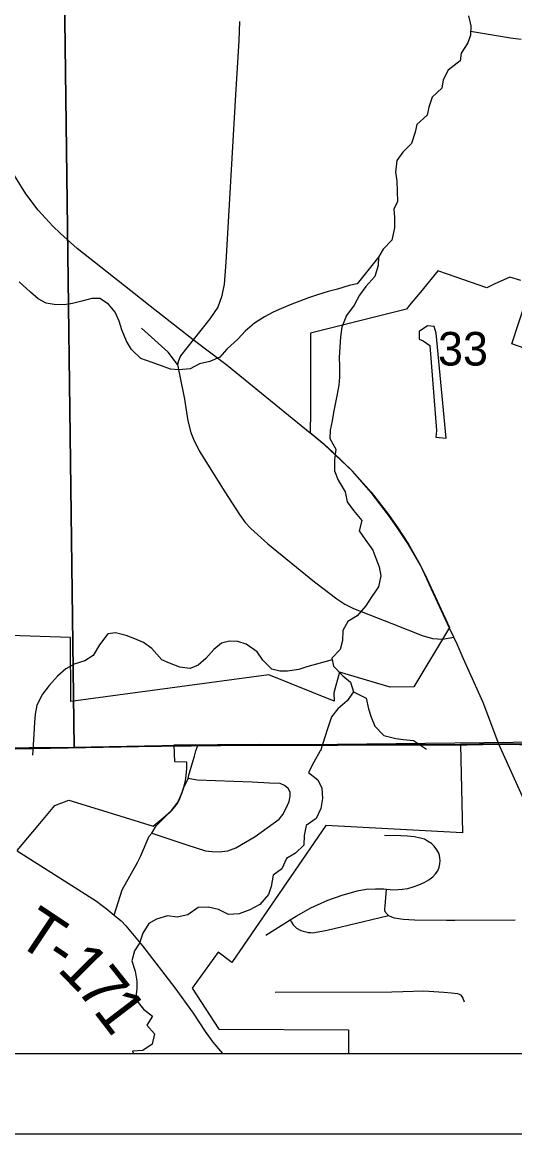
# Model space of a CAD drawing. Extents: x 0 to 36.9, y 0 to 22.
# Drawn here: x 6.188 to 6.801, y 14 to 15.386 of the extents above; entities that cross this region are included whole.
import ezdxf

# ---------------------------------------------------------------- set-up
doc = ezdxf.new("R2010")
doc.units = 0
for name, color, linetype in [('Default', 7, 'Continuous'), ('GM_X_City_Street', 7, 'Continuous'), ('GM_X_County_Road', 7, 'Continuous'), ('GM_X_Major_River', 7, 'Continuous'), ('GM_X_Minor_Lake', 7, 'Continuous'), ('GM_X_Minor_River', 7, 'Continuous'), ('GM_X_Rail_Line', 7, 'Continuous'), ('GM_X_Section', 7, 'Continuous'), ('GM_X_Section_Text', 7, 'Continuous'), ('GM_X_State_Route', 7, 'Continuous'), ('GM_X_Township_Road', 7, 'Continuous'), ('GM_X_Township_Road_Text', 7, 'Continuous'), ('SH_Cut_Line', 7, 'Continuous'), ('SH_Data', 7, 'Continuous')]:
    doc.layers.add(name, color=color, linetype=linetype)

msp = doc.modelspace()

# ---------------------------------------------------------------- linework, layer by layer
at = {"layer": 'Default'}
for points in [[(6.8088, 15.0639), (6.7952, 15.0679), (6.7758, 15.0591), (6.7664, 15.0548), (6.7177, 15.0717), (6.7056, 15.0759), (6.6858, 15.0518), (6.6704, 15.0331), (6.6663, 15.0282), (6.5467, 14.9982), (6.5468, 14.8917), (6.5466, 14.8829), (6.5463, 14.8742), (6.5641, 14.8596), (6.5751, 14.8492), (6.5989, 14.8266), (6.6223, 14.8), (6.644, 14.772), (6.6557, 14.7553), (6.6688, 14.7351), (6.6837, 14.7095), (6.6917, 14.6923), (6.72, 14.631), (6.6757, 14.5571), (6.646, 14.5566), (6.583, 14.5755), (6.576, 14.5497), (6.5762, 14.5395), (6.4949, 14.5722), (6.2485, 14.5389), (6.2478, 14.6189), (6.1594, 14.6218)], [(6.8534, 14.9652), (6.7979, 14.9848), (6.8153, 15.0379)], [(6.1813, 14.3532), (6.2097, 14.3868), (6.2286, 14.4091), (6.2459, 14.416), (6.2984, 14.3998), (6.3509, 14.3835), (6.3659, 14.3958), (6.3736, 14.4031), (6.381, 14.4123), (6.384, 14.4188), (6.3869, 14.426), (6.389, 14.4321), (6.3912, 14.4405), (6.3919, 14.4464), (6.3925, 14.4517), (6.3927, 14.4546), (6.393, 14.4631), (6.3779, 14.4636), (6.377, 14.4847), (6.485, 14.4856), (6.5771, 14.4855), (6.7336, 14.4854), (6.7364, 14.3753), (6.5661, 14.3843), (6.4487, 14.2137), (6.432, 14.2263), (6.3995, 14.1816), (6.4327, 14.1303), (6.5942, 14.1297), (6.5942, 14.1), (7.9756, 14.1)]]:
    msp.add_lwpolyline(points, dxfattribs=at)
at = {"layer": 'GM_X_City_Street'}
msp.add_line((6.844, 14.3471), (6.7814, 14.4858), dxfattribs=at)
for points in [[(6.4911, 14.2476), (6.5216, 14.2667), (6.529, 14.2714), (6.5472, 14.2815), (6.5685, 14.2911), (6.5863, 14.2974), (6.6051, 14.3027), (6.6164, 14.3048), (6.6278, 14.3054), (6.6384, 14.3052), (6.6415, 14.3049), (6.6506, 14.3043), (6.6612, 14.3048), (6.6682, 14.3059), (6.675, 14.3077), (6.6817, 14.3102), (6.6886, 14.3134), (6.6944, 14.3167), (6.6992, 14.3203), (6.7027, 14.3242), (6.7055, 14.328), (6.7073, 14.3323), (6.7081, 14.3364), (6.7083, 14.3405), (6.7082, 14.344), (6.7077, 14.3471), (6.7067, 14.3497), (6.7044, 14.3541), (6.7008, 14.3587), (6.6975, 14.3618), (6.6928, 14.365), (6.6888, 14.3671), (6.684, 14.3686), (6.676, 14.3701), (6.6677, 14.3711), (6.6593, 14.3716), (6.6391, 14.3717)], [(6.6439, 14.2722), (6.6422, 14.2738), (6.6409, 14.2753), (6.6402, 14.2765), (6.6397, 14.2776), (6.6395, 14.2793), (6.6396, 14.2805), (6.6399, 14.2839), (6.6415, 14.3049)], [(6.5216, 14.2667), (6.5232, 14.2637), (6.5252, 14.2606), (6.5272, 14.2583), (6.5296, 14.2562), (6.5349, 14.2536), (6.5379, 14.2525), (6.5412, 14.2516), (6.5442, 14.2511), (6.5472, 14.2508), (6.5497, 14.2507), (6.5517, 14.2509), (6.5676, 14.2538), (6.6129, 14.2645), (6.6439, 14.2722), (6.6477, 14.2704), (6.651, 14.2694), (6.6541, 14.2687), (6.6622, 14.2676), (6.6766, 14.2667), (6.7165, 14.2662), (6.7267, 14.2661), (6.8019, 14.2666)], [(6.5029, 14.1767), (6.6482, 14.177), (6.6619, 14.1774), (6.6881, 14.1781), (6.7128, 14.1766), (6.7227, 14.1759), (6.7263, 14.1755), (6.7299, 14.175), (6.7321, 14.1742), (6.7337, 14.1731), (6.7355, 14.1713), (6.7368, 14.169), (6.7384, 14.1645)]]:
    msp.add_lwpolyline(points, dxfattribs=at)
at = {"layer": 'GM_X_County_Road'}
for points in [[(6.4585, 15.3868), (6.4576, 15.363), (6.4533, 15.2954), (6.4415, 15.0867), (6.4393, 15.0589), (6.436, 15.0433), (6.4313, 15.0306), (6.4216, 15.0161), (6.4006, 14.9897)], [(6.3813, 14.959), (6.3694, 14.9743), (6.3365, 15.0042)], [(6.4006, 14.9897), (6.3851, 14.9697), (6.3823, 14.9637), (6.3813, 14.959), (6.3843, 14.9447), (6.3899, 14.9159), (6.3942, 14.8889), (6.3978, 14.8745), (6.401, 14.8659), (6.4084, 14.8514), (6.4401, 14.8005), (6.4583, 14.7719), (6.4656, 14.762), (6.4724, 14.7547), (6.4937, 14.7356), (6.5519, 14.688), (6.5798, 14.6668), (6.5896, 14.6604), (6.6005, 14.6547), (6.6481, 14.6362), (6.6859, 14.6214), (6.6987, 14.6173), (6.7112, 14.6167), (6.7254, 14.6192)]]:
    msp.add_lwpolyline(points, dxfattribs=at)
at = {"layer": 'GM_X_Major_River'}
for points in [[(6.7438, 15.3937), (6.7467, 15.3812), (6.7461, 15.3698), (6.7429, 15.3603), (6.7347, 15.3472), (6.7334, 15.3377), (6.7184, 15.326), (6.7122, 15.3138), (6.7105, 15.3035), (6.6985, 15.2923), (6.6942, 15.28), (6.6921, 15.2701), (6.6794, 15.2585), (6.6773, 15.2486), (6.6726, 15.2345), (6.6621, 15.2237), (6.6543, 15.2136), (6.6527, 15.1988), (6.6544, 15.1882), (6.6547, 15.1749), (6.6553, 15.1624), (6.6509, 15.1529), (6.6514, 15.1422), (6.6517, 15.1293), (6.6482, 15.1141), (6.6373, 15.1029), (6.6318, 15.0929)], [(6.6318, 15.0929), (6.6312, 15.0827), (6.6269, 15.0689), (6.6158, 15.0562), (6.608, 15.0454), (6.6014, 15.0331), (6.5917, 15.0201), (6.5859, 15.0055), (6.5842, 14.9937), (6.5833, 14.9808), (6.5828, 14.9679), (6.583, 14.9569), (6.5829, 14.9432), (6.5823, 14.9334), (6.5795, 14.92), (6.5778, 14.9097), (6.5757, 14.8991), (6.574, 14.8888), (6.5715, 14.8774), (6.5709, 14.8667), (6.5784, 14.8536), (6.5767, 14.8403), (6.5766, 14.8266), (6.5814, 14.8149), (6.59, 14.8003), (6.5925, 14.7878), (6.6003, 14.7769), (6.6107, 14.7646), (6.6075, 14.7516), (6.6149, 14.7411), (6.6247, 14.7276), (6.6283, 14.7178), (6.6323, 14.7069), (6.6344, 14.6955), (6.6316, 14.6818), (6.6231, 14.6699), (6.6157, 14.658), (6.6049, 14.6457), (6.5936, 14.6386), (6.587, 14.6275), (6.5868, 14.615), (6.584, 14.6039), (6.5735, 14.5931), (6.5756, 14.5829), (6.5872, 14.5709), (6.5969, 14.5631), (6.6005, 14.5511), (6.5927, 14.5399), (6.5811, 14.5298), (6.5729, 14.5198), (6.5675, 14.5038), (6.5592, 14.4774)]]:
    msp.add_lwpolyline(points, dxfattribs=at)
at = {"layer": 'GM_X_Minor_Lake'}
for points in [[(6.7036, 14.9983), (6.7008, 15.0066), (6.6928, 15.0072), (6.6823, 15.0002), (6.6821, 14.9907), (6.6874, 14.9885), (6.6955, 14.9826), (6.7037, 14.8768), (6.7031, 14.8684), (6.716, 14.8671)], [(6.716, 14.8671), (6.7036, 14.9983)]]:
    msp.add_lwpolyline(points, dxfattribs=at)
at = {"layer": 'GM_X_Minor_River'}
for points in [[(6.7463, 15.3745), (6.7959, 15.3665), (6.8092, 15.3645)], [(6.6318, 15.0929), (6.6049, 15.0597), (6.5951, 15.0576), (6.5807, 15.0532), (6.5689, 15.05), (6.5557, 15.0459), (6.5444, 15.042), (6.5338, 15.038), (6.5236, 15.0344), (6.5107, 15.0289), (6.5002, 15.0245), (6.4896, 15.0186), (6.4772, 15.0108), (6.4656, 15.0008), (6.457, 14.9911), (6.4427, 14.9784), (6.4338, 14.9684), (6.4213, 14.9628), (6.4088, 14.96), (6.3971, 14.9537), (6.3827, 14.9523), (6.3724, 14.9533), (6.3613, 14.9573), (6.3495, 14.9616), (6.3357, 14.9667), (6.3241, 14.9776), (6.3175, 14.9881), (6.3119, 15.0024), (6.3087, 15.013), (6.3036, 15.0243), (6.2954, 15.0344), (6.2843, 15.0414), (6.2744, 15.0413), (6.2619, 15.038), (6.2506, 15.0352), (6.24, 15.0335), (6.2274, 15.0337), (6.2175, 15.0354), (6.2075, 15.0409), (6.1979, 15.0491), (6.184, 15.0622)], [(6.574, 14.5909), (6.5422, 14.5823), (6.5324, 14.5787), (6.5184, 14.5769), (6.5089, 14.5767), (6.4986, 14.5792), (6.4874, 14.5904), (6.4804, 14.6009), (6.4669, 14.6105), (6.4562, 14.6138), (6.446, 14.6143), (6.4361, 14.6115), (6.4264, 14.6037), (6.4167, 14.5926), (6.407, 14.5844), (6.3968, 14.5801), (6.3843, 14.5817), (6.3713, 14.5868), (6.3617, 14.5908), (6.3493, 14.605), (6.3389, 14.6124), (6.3282, 14.6172), (6.3171, 14.6211), (6.3041, 14.6247), (6.2943, 14.6234), (6.2839, 14.6095), (6.2762, 14.5961), (6.2657, 14.5898), (6.2524, 14.5854), (6.2423, 14.5796), (6.2318, 14.5706), (6.2214, 14.5587), (6.2129, 14.5479), (6.2059, 14.5345), (6.2038, 14.5231), (6.2032, 14.5128), (6.2024, 14.4984), (6.2008, 14.4721)], [(6.6005, 14.5511), (6.6162, 14.543), (6.6191, 14.5298), (6.6223, 14.5192), (6.6271, 14.5083), (6.6383, 14.4967), (6.6532, 14.4928), (6.6627, 14.4915), (6.6752, 14.4905), (6.6913, 14.4793)], [(6.5591, 14.4775), (6.5512, 14.4633), (6.5443, 14.4506), (6.5562, 14.4413), (6.5609, 14.4308), (6.5619, 14.4179), (6.5598, 14.4057), (6.5539, 14.3931), (6.5416, 14.3842), (6.5391, 14.372), (6.5386, 14.3598), (6.5281, 14.3498), (6.5169, 14.3432), (6.5114, 14.3305), (6.5002, 14.3224), (6.4977, 14.3083), (6.4945, 14.2984), (6.4837, 14.2857), (6.4713, 14.279), (6.4581, 14.2742), (6.4449, 14.2732), (6.4323, 14.2795), (6.4197, 14.2827), (6.4068, 14.2821), (6.3941, 14.2731), (6.3809, 14.2699), (6.3687, 14.2719), (6.3551, 14.2675), (6.3454, 14.262), (6.338, 14.2501), (6.3337, 14.2376), (6.3277, 14.228), (6.3242, 14.2154), (6.3285, 14.2029), (6.3307, 14.1901), (6.3304, 14.1806), (6.3291, 14.1677), (6.3388, 14.1553), (6.35, 14.1468), (6.343, 14.1353), (6.3526, 14.1248), (6.3498, 14.1119), (6.3382, 14.1037), (6.3253, 14.1031), (6.3265, 14.1)]]:
    msp.add_lwpolyline(points, dxfattribs=at)
at = {"layer": 'GM_X_Rail_Line'}
msp.add_lwpolyline([(5.2462, 14.4712), (5.4467, 14.4748), (5.4581, 14.475), (5.4676, 14.4751), (5.9207, 14.4754), (6.4063, 14.4846), (6.5807, 14.485), (6.7336, 14.4854), (6.7812, 14.4863), (6.8569, 14.4852), (7.1313, 14.488), (7.4027, 14.4935), (7.7356, 14.4946), (7.9858, 14.497), (8.6137, 14.5116), (8.9, 14.5158), (8.9, 20.5927)], dxfattribs=at)
msp.add_lwpolyline([(4.2643, 14.1), (8.9, 14.1), (8.9, 14.5158), (8.6137, 14.5116), (7.9858, 14.497), (7.7356, 14.4946), (7.4027, 14.4935), (7.1313, 14.488), (6.8569, 14.4852), (6.7812, 14.4863), (6.7336, 14.4854), (6.5807, 14.485), (6.4063, 14.4846), (5.9207, 14.4754), (5.4676, 14.4751), (5.4581, 14.475), (5.4467, 14.4748), (5.2462, 14.4712), (5.1185, 14.4712), (4.6008, 14.4672), (4.262, 14.4619)], close=True, dxfattribs=at)
at = {"layer": 'GM_X_Section'}
for points in [[(6.2395, 15.4861), (7.2257, 15.5025), (7.2369, 14.4927), (6.2525, 14.4815)], [(5.2381, 15.4765), (6.2395, 15.4861), (6.2525, 14.4815), (5.2461, 14.474)]]:
    msp.add_lwpolyline(points, close=True, dxfattribs=at)
at = {"layer": 'GM_X_State_Route'}
for p, q in [((6.7372, 14.5928), (6.7294, 14.6104)), ((6.0398, 14.4771), (6.3767, 14.4835)), ((6.7417, 14.485), (6.7814, 14.4858)), ((6.7814, 14.4858), (6.8571, 14.4846))]:
    msp.add_line(p, q, dxfattribs=at)
for points in [[(6.3231, 15.051), (6.2562, 15.1039), (6.2353, 15.1223), (6.2258, 15.1314), (6.2075, 15.1513), (6.1924, 15.1718), (6.1795, 15.1927), (6.1563, 15.2327), (6.0155, 15.4812), (5.8461, 15.7824), (5.7784, 15.9063), (5.7307, 15.9951), (5.6955, 16.0767), (5.6648, 16.1701), (5.6378, 16.2518), (5.6249, 16.2792), (5.5961, 16.329), (5.5806, 16.3575), (5.5514, 16.4121), (5.5432, 16.4273), (5.5369, 16.4383), (5.504, 16.4959), (5.45, 16.5871)], [(6.5527, 14.8686), (6.5465, 14.8736), (6.4432, 14.9579), (6.4006, 14.9897), (6.3472, 15.0319), (6.3231, 15.051)], [(6.6953, 14.6843), (6.6919, 14.6917), (6.6839, 14.709), (6.669, 14.7345), (6.6559, 14.7547), (6.6442, 14.7714), (6.6225, 14.7995), (6.5991, 14.8261), (6.5643, 14.8591), (6.5527, 14.8686)], [(6.7294, 14.6104), (6.7254, 14.6192), (6.7202, 14.6305), (6.6953, 14.6843)], [(6.7814, 14.4858), (6.762, 14.5375), (6.7372, 14.5928)], [(6.3767, 14.4835), (6.4065, 14.4841), (6.574, 14.4845)], [(6.574, 14.4845), (6.5809, 14.4845), (6.6825, 14.4847)], [(6.6825, 14.4847), (6.7337, 14.4848), (6.7417, 14.485)]]:
    msp.add_lwpolyline(points, dxfattribs=at)
at = {"layer": 'GM_X_Township_Road'}
for points in [[(6.4022, 14.4706), (6.4042, 14.4775), (6.4065, 14.4841)], [(6.3548, 14.3839), (6.3656, 14.3948), (6.3742, 14.4029), (6.3812, 14.4117), (6.3842, 14.4182), (6.3871, 14.4255), (6.3892, 14.4316), (6.3946, 14.4428), (6.3958, 14.4487), (6.4022, 14.4706)], [(6.3493, 14.3747), (6.3927, 14.3602), (6.4163, 14.3529), (6.4246, 14.3518), (6.4331, 14.3516), (6.4438, 14.3529), (6.4539, 14.3566), (6.4779, 14.3706), (6.5006, 14.3869), (6.508, 14.3923), (6.5126, 14.398), (6.5166, 14.4061), (6.5203, 14.4141), (6.5214, 14.4211), (6.5214, 14.4259), (6.5189, 14.4304), (6.5144, 14.4344), (6.5093, 14.4368), (6.4957, 14.437), (6.4741, 14.4382), (6.4057, 14.4409), (6.3946, 14.4428)], [(6.3312, 14.3384), (6.3352, 14.3456), (6.346, 14.3709), (6.3493, 14.3747), (6.3548, 14.3839)], [(6.1814, 14.3527), (6.2576, 14.3047), (6.2802, 14.2898), (6.2859, 14.2858), (6.2925, 14.2808), (6.3024, 14.2727), (6.3109, 14.2653), (6.3169, 14.2592), (6.3377, 14.2343), (6.3777, 14.1821), (6.4006, 14.1502), (6.4157, 14.1273), (6.4254, 14.1142), (6.4347, 14.103), (6.4372, 14.1)], [(6.3024, 14.2727), (6.3121, 14.304), (6.3312, 14.3384)]]:
    msp.add_lwpolyline(points, dxfattribs=at)
at = {"layer": 'SH_Cut_Line'}
for points in [[(5.2462, 14.4712), (5.4467, 14.4748), (5.4581, 14.475), (5.4676, 14.4751), (5.9207, 14.4754), (6.4063, 14.4846), (6.5807, 14.485), (6.7336, 14.4854), (6.7812, 14.4863), (6.8569, 14.4852), (7.1313, 14.488), (7.4027, 14.4935), (7.7356, 14.4946), (7.9858, 14.497), (8.6137, 14.5116), (8.9, 14.5158), (8.9, 20.9)], [(2.1, 14.1), (8.9, 14.1), (8.9, 14.5158), (8.6137, 14.5116), (7.9858, 14.497), (7.7356, 14.4946), (7.4027, 14.4935), (7.1313, 14.488), (6.8569, 14.4852), (6.7812, 14.4863), (6.7336, 14.4854), (6.5807, 14.485), (6.4063, 14.4846), (5.9207, 14.4754), (5.4676, 14.4751), (5.4581, 14.475), (5.4467, 14.4748), (5.2462, 14.4712)]]:
    msp.add_lwpolyline(points, dxfattribs=at)
at = {"layer": 'SH_Data'}
for p, q in [((2.1, 14.1), (8.9, 14.1)), ((2, 14), (9, 14))]:
    msp.add_line(p, q, dxfattribs=at)

# ---------------------------------------------------------------- texts
at = {"layer": 'GM_X_Section_Text'}
msp.add_text('33', height=0.04186, rotation=0, dxfattribs=at).set_placement((6.7057, 14.9578))
at = {"layer": 'GM_X_Township_Road_Text'}
for s, rotation, p in [('T', 326.2945, (6.1779, 14.2388)), ('-', 325.7773, (6.2131, 14.2153)), ('1', 314.7093, (6.2302, 14.204)), ('7', 308.3689, (6.2537, 14.1804)), ('1', 307.4642, (6.2753, 14.1531))]:
    msp.add_text(s, height=0.0568, rotation=rotation, dxfattribs=at).set_placement(p)

doc.saveas('drawing.dxf')
